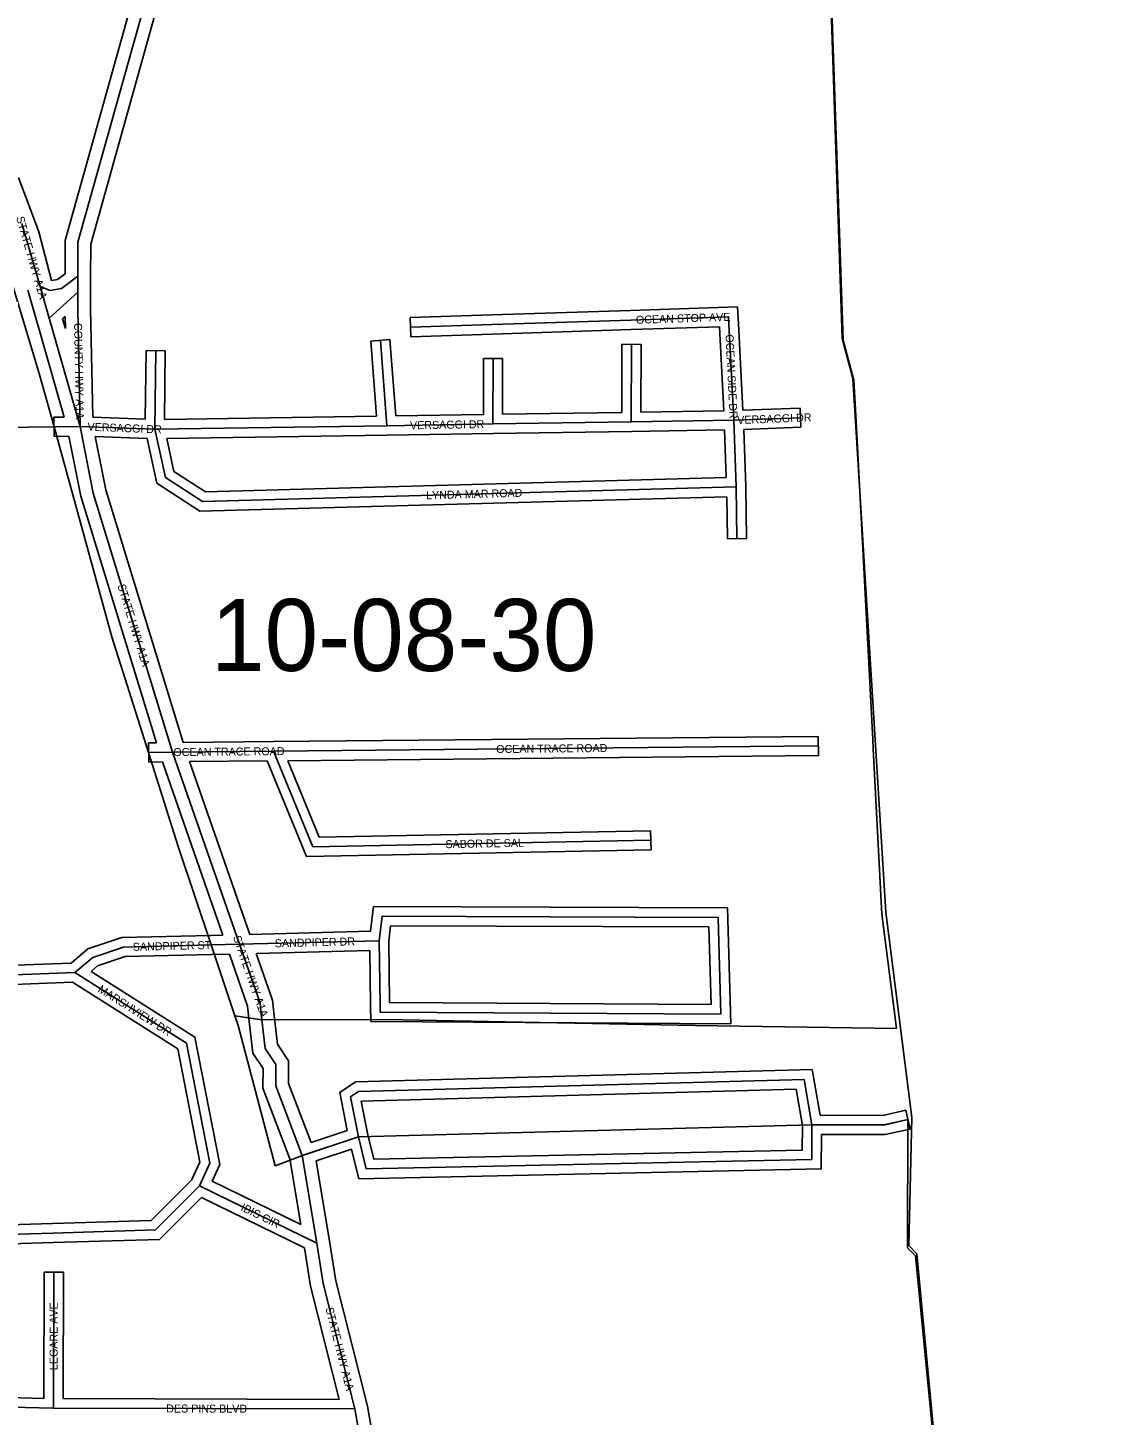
# Model space of a CAD drawing. Extents: x 418523 to 616617, y 1878279 to 2196743.
# Drawn here: x 569974 to 573384, y 1993241 to 1997576 of the extents above; entities that cross this region are included whole.
import ezdxf

# ---------------------------------------------------------------- set-up
doc = ezdxf.new("R2010")
doc.units = 0
for name, color, linetype in [('Level 2', 7, 'Continuous'), ('Level 22', 7, 'Continuous'), ('Level 23', 7, 'Continuous'), ('Level 31', 7, 'Continuous'), ('Level 32', 7, 'Continuous'), ('Level 34', 7, 'Continuous'), ('Level 5', 7, 'Continuous'), ('Level 8', 7, 'Continuous')]:
    doc.layers.add(name, color=color, linetype=linetype)

msp = doc.modelspace()

# ---------------------------------------------------------------- linework, layer by layer
at = {"layer": 'Level 22'}
for p, q in [((570012.083, 1996767.13), (569955.466, 1996964.365)), ((570130.005, 1996749.761), (570130.122, 1996799.582)), ((570040.392, 1996668.876), (570012.083, 1996767.13)), ((570635.491, 1994712.468), (570426.32, 1995312.626)), ((570705.344, 1994475.929), (570703.168, 1994494.844)), ((570876.56, 1993778.402), (570831.529, 1994052.704)), ((571037.193, 1993026.716), (570995.871, 1993260.28))]:
    msp.add_line(p, q, dxfattribs=at)
for points in [[(570130.122, 1996799.582), (570130.37, 1996905.77), (570458.774, 1998079.976), (570920.756, 1999437.885)], [(570137.269, 1996330.448), (570129.882, 1996697.031), (570130.005, 1996749.761)], [(570137.269, 1996330.448), (570049.512, 1996636.489), (570040.392, 1996668.876)], [(570426.32, 1995312.626), (570178.324, 1996121.977), (570137.269, 1996330.448)], [(570703.168, 1994494.844), (570699.44, 1994528.31), (570635.491, 1994712.468)], [(570831.529, 1994052.704), (570748.628, 1994269.635), (570748.782, 1994336.184), (570715.6, 1994386.446), (570705.344, 1994475.929)], [(570995.871, 1993260.28), (570896.88, 1993652.166), (570876.56, 1993778.402)]]:
    msp.add_lwpolyline(points, dxfattribs=at)
at = {"layer": 'Level 23'}
for p, q in [((570007.837, 1996938.141), (569944.724, 1997108.546)), ((570048.124, 1996786.621), (570007.837, 1996938.141)), ((570170.006, 1996749.667), (570170.123, 1996799.487)), ((570001.889, 1996658.034), (569973.646, 1996756.055)), ((570091.095, 1996636.391), (570082.601, 1996666.559)), ((570091.095, 1996636.391), (570090.347, 1996673.55)), ((570583.152, 1994741.1), (570394.552, 1995282.236)), ((570667.116, 1994743.273), (570478.969, 1995283.106)), ((570665.605, 1994471.357), (570663.429, 1994490.271)), ((570745.083, 1994480.501), (570742.907, 1994499.415)), ((570826.519, 1993836.3), (570792.715, 1994042.216)), ((570916.034, 1993784.882), (570874.904, 1994035.418)), ((571072.487, 1993056.834), (571035.009, 1993268.671))]:
    msp.add_line(p, q, dxfattribs=at)
for points in [[(570090.14, 1996807.221), (570090.382, 1996911.304), (570420.549, 1998091.813), (570882.072, 1999448.369)], [(570170.123, 1996799.488), (570170.358, 1996900.235), (570496.999, 1998068.137), (570952.771, 1999407.791)], [(570176.705, 1996358.965), (570169.884, 1996697.388), (570170.006, 1996749.668)], [(570087.277, 1996359.672), (570011.034, 1996625.555), (570001.889, 1996658.034)], [(570375.48, 1995342.009), (570139.474, 1996112.227), (570102.517, 1996299.902)], [(570458.874, 1995342.926), (570217.173, 1996131.727), (570184.305, 1996298.629)], [(570663.413, 1994490.416), (570660.182, 1994519.425), (570603.859, 1994681.623)], [(570742.923, 1994499.271), (570738.699, 1994537.194), (570687.799, 1994683.774)], [(570792.715, 1994042.216), (570708.609, 1994262.296), (570708.754, 1994324.213), (570676.949, 1994372.389), (570665.603, 1994471.375)], [(570858.839, 1994093.3), (570788.646, 1994276.973), (570788.811, 1994348.155), (570754.252, 1994400.502), (570745.084, 1994480.484)], [(570947.003, 1993290.412), (570857.667, 1993644.074), (570838.416, 1993763.671)], [(571035.009, 1993268.671), (570936.094, 1993660.258), (570916.053, 1993784.76)]]:
    msp.add_lwpolyline(points, dxfattribs=at)
at = {"layer": 'Level 31'}
for p, q in [((570040.392, 1996668.876), (570130.005, 1996749.761)), ((571858.349, 1996662.836), (571424.832, 1996648.561)), ((571424.832, 1996648.561), (571169.225, 1996640.425)), ((572179.814, 1996349.719), (572164.644, 1996649.406)), ((570370.641, 1996321.537), (570373.434, 1996567.363)), ((571095.896, 1996332.578), (571075.584, 1996599.185)), ((571859.523, 1996344.635), (571860.078, 1996586.828)), ((571427.288, 1996337.993), (571427.442, 1996542.731)), ((572179.814, 1996349.719), (572388.174, 1996357.606)), ((570056.086, 1996329.184), (570137.269, 1996330.448)), ((570370.641, 1996321.537), (570137.269, 1996330.448)), ((570370.641, 1996321.537), (571095.896, 1996332.578)), ((571095.896, 1996332.578), (571427.288, 1996337.993)), ((571427.288, 1996337.993), (571859.523, 1996344.635)), ((571859.523, 1996344.635), (572179.814, 1996349.719)), ((572187.584, 1996141.326), (572179.814, 1996349.719)), ((572187.584, 1996141.326), (572189.752, 1995979.858)), ((570351.161, 1995311.711), (570426.32, 1995312.626)), ((570426.32, 1995312.626), (570741.859, 1995315.526)), ((570741.859, 1995315.526), (572443.869, 1995331.969)), ((570546.692, 1994710.129), (570635.491, 1994712.468)), ((570635.491, 1994712.468), (571071.879, 1994723.455)), ((571074.589, 1994523.801), (571071.879, 1994723.455)), ((570121.228, 1994624.211), (569530.371, 1994601.236)), ((571074.851, 1994500.526), (571074.589, 1994523.801)), ((572139.744, 1994494.074), (571074.851, 1994500.526)), ((572648.894, 1994147.802), (572424.052, 1994148.315)), ((572648.894, 1994147.802), (572724.091, 1994164.36)), ((570831.529, 1994052.704), (571006.719, 1994110.481)), ((570876.56, 1993778.402), (570510.057, 1993957.811)), ((570053.983, 1993262.84), (570055.295, 1993687.951)), ((570053.983, 1993262.84), (569262.138, 1993281.434)), ((570053.983, 1993262.84), (570995.871, 1993260.28))]:
    msp.add_line(p, q, dxfattribs=at)
for points in [[(570130.122, 1996799.582), (570078.979, 1996761.518), (570043.765, 1996755.418), (570012.083, 1996767.13)], [(572164.644, 1996649.406), (572163.429, 1996672.683), (571858.349, 1996662.836)], [(570370.641, 1996321.537), (570403.587, 1996171.271), (570520.109, 1996096.086), (572187.584, 1996141.326)], [(570741.859, 1995315.526), (570864.527, 1995017.042), (571920.585, 1995037.151)], [(571071.879, 1994723.455), (571080.935, 1994799.801), (572130.919, 1994796.292), (572139.744, 1994494.074)], [(570121.228, 1994624.211), (570176.835, 1994671.356), (570273.316, 1994703.496), (570546.692, 1994710.129)], [(570510.057, 1993957.811), (570542.249, 1994027.921), (570469.234, 1994403.748), (570121.228, 1994624.211)], [(571006.719, 1994110.481), (570981.954, 1994235.636), (571007.047, 1994252.306), (572399.321, 1994290.196), (572424.052, 1994148.315)], [(571006.719, 1994110.481), (571031.222, 1994010.42), (572423.489, 1994039.946), (572424.052, 1994148.315)], [(570052.409, 1993810.146), (570372.418, 1993819.942), (570510.057, 1993957.811)], [(569316.513, 1993880.247), (569421.907, 1993790.902), (570052.409, 1993810.146)]]:
    msp.add_lwpolyline(points, dxfattribs=at)
at = {"layer": 'Level 32'}
for p, q in [((570082.601, 1996666.559), (570090.347, 1996673.55)), ((571423.878, 1996678.546), (571168.271, 1996670.41)), ((571170.18, 1996610.439), (571168.271, 1996670.41)), ((571857.362, 1996692.821), (571423.844, 1996678.546)), ((571425.787, 1996618.576), (571170.18, 1996610.439)), ((571859.338, 1996632.852), (571425.82, 1996618.577)), ((572134.993, 1996641.75), (571859.318, 1996632.852)), ((572148.283, 1996379.221), (572134.993, 1996641.75)), ((572208.279, 1996380.818), (572194.606, 1996650.922)), ((570340.994, 1996352.691), (570343.436, 1996567.704)), ((570343.436, 1996567.704), (570403.434, 1996567.022)), ((571045.669, 1996596.905), (571105.499, 1996601.463)), ((571063.56, 1996362.089), (571045.669, 1996596.905)), ((571123.664, 1996363.036), (571105.499, 1996601.463)), ((571829.591, 1996374.178), (571830.078, 1996586.897)), ((571830.078, 1996586.897), (571890.079, 1996586.759)), ((571889.594, 1996375.115), (571890.079, 1996586.759)), ((570400.99, 1996352.003), (570403.434, 1996567.022)), ((571397.31, 1996367.507), (571397.443, 1996542.753)), ((571397.443, 1996542.753), (571457.443, 1996542.708)), ((571457.312, 1996368.458), (571457.443, 1996542.708)), ((570055.619, 1996359.181), (570087.277, 1996359.673)), ((570055.619, 1996359.181), (570056.554, 1996299.186)), ((570340.994, 1996352.691), (570176.705, 1996358.965)), ((570400.99, 1996352.003), (571063.56, 1996362.089)), ((571123.664, 1996363.036), (571397.31, 1996367.507)), ((571457.312, 1996368.457), (571829.591, 1996374.178)), ((571889.594, 1996375.116), (572148.283, 1996379.221)), ((572208.28, 1996380.818), (572387.039, 1996387.586)), ((572387.039, 1996387.586), (572389.309, 1996327.626)), ((571096.386, 1996302.581), (571427.778, 1996307.996)), ((571427.749, 1996307.996), (571859.984, 1996314.637)), ((571859.999, 1996314.637), (572150.929, 1996319.255)), ((572156.474, 1996170.493), (572150.929, 1996319.255)), ((572210.913, 1996320.872), (572389.309, 1996327.626)), ((572217.578, 1996142.086), (572210.913, 1996320.872)), ((570056.554, 1996299.186), (570102.517, 1996299.902)), ((570346.307, 1996292.443), (570184.305, 1996298.629)), ((570407.81, 1996292.099), (571096.353, 1996302.581)), ((572217.578, 1996142.085), (572219.75, 1995980.26)), ((572157.995, 1996110.511), (572159.754, 1995979.455)), ((572219.75, 1995980.26), (572159.754, 1995979.455)), ((570741.57, 1995345.526), (572443.58, 1995361.968)), ((572443.58, 1995361.968), (572444.16, 1995301.969)), ((570350.797, 1995341.708), (570375.481, 1995342.009)), ((570350.797, 1995341.708), (570351.527, 1995281.711)), ((570458.874, 1995342.926), (570741.584, 1995345.526)), ((570351.527, 1995281.711), (570394.552, 1995282.234)), ((570478.969, 1995283.106), (570721.83, 1995285.34)), ((570786.449, 1995285.954), (572444.16, 1995301.969)), ((571920.014, 1995067.146), (571921.156, 1995007.156)), ((570667.116, 1994743.273), (571045.149, 1994752.791)), ((570545.902, 1994740.119), (570583.152, 1994741.1)), ((571104.503, 1994530.347), (571101.904, 1994721.883)), ((570547.482, 1994680.138), (570603.859, 1994681.622)), ((570687.799, 1994683.774), (571042.294, 1994692.698)), ((571044.59, 1994523.461), (571042.294, 1994692.699)), ((570109.721, 1994653.786), (569543.916, 1994631.785)), ((570113.064, 1994593.869), (569549.945, 1994571.972)), ((572108.849, 1994524.261), (571104.503, 1994530.347)), ((571045.187, 1994470.703), (571044.59, 1994523.461)), ((572170.639, 1994463.884), (571045.187, 1994470.703)), ((572645.665, 1994177.81), (572717.641, 1994193.657)), ((572717.641, 1994193.657), (572730.543, 1994135.061)), ((572645.665, 1994177.81), (572449.286, 1994178.256)), ((570858.838, 1994093.299), (570972.142, 1994130.667)), ((572652.124, 1994117.793), (572453.898, 1994118.245)), ((572652.124, 1994117.793), (572730.543, 1994135.061)), ((570874.904, 1994035.418), (570985.299, 1994071.826)), ((570826.519, 1993836.3), (570549.534, 1993971.887)), ((570838.416, 1993763.671), (570516.134, 1993921.433)), ((570024.078, 1993293.551), (570025.295, 1993688.042)), ((570025.295, 1993688.042), (570085.295, 1993687.857)), ((570084.076, 1993292.758), (570085.295, 1993687.857)), ((570024.077, 1993293.551), (569282.18, 1993310.971)), ((570084.077, 1993292.758), (570947.003, 1993290.412))]:
    msp.add_line(p, q, dxfattribs=at)
for points in [[(570090.139, 1996807.221), (570066.807, 1996789.857), (570048.124, 1996786.621)], [(572194.604, 1996650.971), (572191.854, 1996703.617), (571857.381, 1996692.821)], [(570346.308, 1996292.443), (570376.931, 1996152.767), (570511.644, 1996065.844), (572157.994, 1996110.511)], [(570407.809, 1996292.098), (570430.244, 1996189.776), (570528.574, 1996126.327), (572156.475, 1996170.493)], [(570721.831, 1995285.34), (570844.579, 1994986.656), (571921.156, 1995007.156)], [(570786.449, 1995285.954), (570884.474, 1995047.429), (571920.014, 1995067.146)], [(571045.149, 1994752.791), (571054.294, 1994829.891), (572160.059, 1994826.196), (572170.639, 1994463.885)], [(571101.904, 1994721.883), (571107.577, 1994769.711), (572101.779, 1994766.388), (572108.849, 1994524.261)], [(570109.721, 1994653.786), (570161.855, 1994697.986), (570268.097, 1994733.379), (570545.964, 1994740.121)], [(570171.756, 1994627.716), (570191.815, 1994644.724), (570278.535, 1994673.612), (570547.419, 1994680.137)], [(570549.534, 1993971.888), (570573.539, 1994024.171), (570496.217, 1994422.168), (570171.756, 1994627.715)], [(570485.034, 1993975.206), (570510.959, 1994031.671), (570442.252, 1994385.328), (570113.063, 1994593.869)], [(570972.143, 1994130.668), (570948.627, 1994249.513), (570997.62, 1994282.061), (572424.424, 1994320.891), (572449.287, 1994178.257)], [(571036.019, 1994116.963), (571015.282, 1994221.76), (571016.473, 1994222.551), (572374.219, 1994259.501), (572394.039, 1994145.796)], [(571036.018, 1994116.963), (571054.639, 1994040.924), (572393.64, 1994069.321), (572394.039, 1994145.796)], [(570985.299, 1994071.826), (571007.805, 1993979.915), (572453.336, 1994010.571), (572453.898, 1994118.245)], [(570051.491, 1993840.132), (570359.599, 1993849.565), (570485.034, 1993975.207)], [(569335.912, 1993903.131), (569432.514, 1993821.241), (570051.494, 1993840.132)], [(570053.328, 1993780.159), (570385.237, 1993790.321), (570516.134, 1993921.433)], [(569324.111, 1993834.476), (569411.301, 1993760.564), (570053.325, 1993780.159)]]:
    msp.add_lwpolyline(points, dxfattribs=at)
at = {"layer": 'Level 5'}
msp.add_lwpolyline([(572465.57, 1998189.806), (572518.829, 1996605.731), (572551.753, 1996480.558), (572654.735, 1994812.961), (572736.049, 1994170.798), (572726.405, 1993770.689), (572751.346, 1993745.579), (572912.59, 1992052.782), (573180.964, 1989967.808), (573303.759, 1989275.465), (573319.554, 1989000.338), (573638.437, 1987065.259)], dxfattribs=at)
at = {"layer": 'Level 8'}
for points in [[(572467.73, 1998183.396), (572521.759, 1996599.361), (572554.763, 1996474.358), (572560.765, 1996364.356), (572613.784, 1995352.333), (572615.784, 1995323.332), (572642.794, 1994806.321), (572680.801, 1994506.315), (572687.802, 1994449.314), (572059.787, 1994458.306), (571089.764, 1994477.294), (570705.754, 1994476.289), (570620.753, 1994488.288), (570546.747, 1994710.292), (570443.739, 1995018.298), (570350.731, 1995311.304), (570236.722, 1995673.311), (570055.706, 1996329.323), (570009.702, 1996495.326), (569858.689, 1996994.336), (569834.687, 1997093.337), (569704.675, 1997603.347)], [(569053.683, 1996316.31), (570055.706, 1996329.323), (570236.722, 1995673.311), (570350.731, 1995311.304), (570443.739, 1995018.298), (570546.747, 1994710.292), (570620.753, 1994488.288)], [(570620.753, 1994488.288), (570630.753, 1994458.288), (570746.764, 1994020.279), (570831.765, 1994052.281), (571006.769, 1994110.285), (572423.801, 1994148.304), (572648.807, 1994147.306), (572723.808, 1994164.308), (572722.815, 1993764.299), (572747.816, 1993739.298), (572815.83, 1993034.283), (572909.85, 1992046.262), (573078.878, 1990741.235), (573179.894, 1989961.218), (573302.909, 1989269.204), (573318.914, 1988994.198), (573638.957, 1987059.159)]]:
    msp.add_lwpolyline(points, dxfattribs=at)

# ---------------------------------------------------------------- texts
at = {"layer": 'Level 2'}
msp.add_text('10-08-30', height=225, dxfattribs=at).set_placement((570546.277, 1995566.322))
at = {"layer": 'Level 34'}
for s, height, rotation, p in [('STATE HWY A1A', 25, 286.015222, (569937.197, 1996982.713)), ('OCEAN STOP AVE', 24.99916, 1.847869, (571874.366, 1996650.85)), ('COUNTY HWY A1A', 25, 271.153433, (570118.26, 1996653.381)), ('OCEAN SIDE DR', 25, 272.896989, (572153.751, 1996617.364)), ('VERSAGGI DR', 25, 2.167308, (572190.989, 1996337.634)), ('VERSAGGI DR', 25, 357.812711, (570160.002, 1996317.073)), ('VERSAGGI DR', 25, 0.935503, (571168.264, 1996321.26)), ('LYNDA MAR ROAD', 25, 1.553389, (571218.644, 1996102.535)), ('STATE HWY A1A', 25, 287.034808, (570253.67, 1995833.42)), ('OCEAN TRACE ROAD', 24.99916, 0.525992, (570428.784, 1995300.151)), ('OCEAN TRACE ROAD', 25, 0.552792, (571437.558, 1995309.75)), ('SABOR DE SAL', 25, 1.090075, (571278.956, 1995012.433)), ('SANDPIPER ST', 25, 1.389486, (570302.149, 1994691.693)), ('STATE HWY A1A', 25, 289.148278, (570614.565, 1994734.634)), ('SANDPIPER DR', 25, 1.441439, (570745.844, 1994702.745)), ('MARSHVIEW DR', 25, 327.644825, (570190.763, 1994565.364)), ('IBIS CIR', 25, 333.916814, (570636.894, 1993881.806)), ('LEGARE AVE', 25, 89.822133, (570066.848, 1993381.815)), ('STATE HWY A1A', 25, 284.175197, (570903.578, 1993574.622)), ('DES PINS BLVD', 25, 359.843494, (570406.309, 1993249.384))]:
    msp.add_text(s, height=height, rotation=rotation, dxfattribs=at).set_placement(p)

doc.saveas('drawing.dxf')
